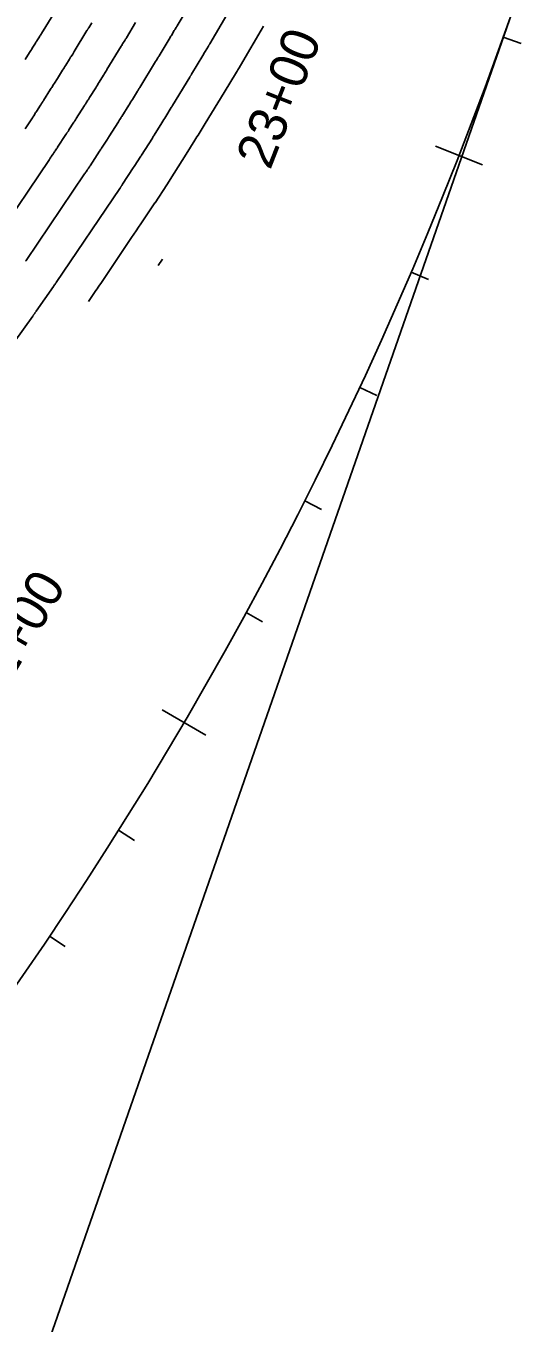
# Model space of a CAD drawing. Extents: x 1710723 to 1713003, y 548603 to 551142.
# Drawn here: x 1712301.3 to 1712379.8, y 549302.6 to 549508.2 of the extents above; entities that cross this region are included whole.
import ezdxf

# ---------------------------------------------------------------- set-up
doc = ezdxf.new("R2010")
doc.units = 0
for name, color, linetype in [('R_Contours', 7, 'Continuous'), ('R_Horz Alg', 7, 'Continuous'), ('R_Horz Alg Annot', 7, 'Continuous')]:
    doc.layers.add(name, color=color, linetype=linetype)

msp = doc.modelspace()

# ---------------------------------------------------------------- linework, layer by layer
at = {"layer": 'R_Contours'}
for points in [[(1712301.23, 549470.93), (1712301.28, 549471), (1712301.32, 549471.06), (1712310.57, 549484.76), (1712310.59, 549484.79), (1712310.61, 549484.82), (1712310.63, 549484.85), (1712310.65, 549484.88), (1712310.73, 549485), (1712310.75, 549485.03), (1712310.77, 549485.06), (1712310.79, 549485.08), (1712310.81, 549485.11), (1712310.97, 549485.35), (1712311.01, 549485.4), (1712311.05, 549485.45), (1712311.12, 549485.56), (1712311.14, 549485.59), (1712311.16, 549485.61), (1712311.18, 549485.64), (1712311.19, 549485.67), (1712311.33, 549485.88), (1712311.36, 549485.92), (1712311.39, 549485.97), (1712311.42, 549486.01), (1712311.45, 549486.06), (1712312.95, 549488.36), (1712313.01, 549488.44), (1712313.06, 549488.52), (1712313.16, 549488.68), (1712313.19, 549488.72), (1712313.22, 549488.76), (1712313.24, 549488.8), (1712313.27, 549488.84), (1712314.19, 549490.26), (1712314.23, 549490.32), (1712314.27, 549490.38), (1712314.35, 549490.51), (1712314.37, 549490.54), (1712314.39, 549490.57), (1712314.41, 549490.6), (1712314.43, 549490.63), (1712315.94, 549493.03), (1712315.98, 549493.1), (1712316.03, 549493.17), (1712316.07, 549493.25), (1712316.12, 549493.32), (1712316.3, 549493.6), (1712316.34, 549493.67), (1712316.39, 549493.74), (1712316.43, 549493.81), (1712316.48, 549493.88), (1712317.58, 549495.65), (1712317.72, 549495.88), (1712317.86, 549496.11), (1712318.01, 549496.34), (1712318.15, 549496.57), (1712318.94, 549497.85), (1712318.97, 549497.9), (1712319, 549497.95), (1712319.03, 549498), (1712319.06, 549498.05), (1712319.19, 549498.26), (1712319.22, 549498.31), (1712319.26, 549498.36), (1712319.29, 549498.41), (1712319.32, 549498.46), (1712321.82, 549502.56), (1712321.83, 549502.58), (1712321.84, 549502.6), (1712321.86, 549502.62), (1712321.87, 549502.64), (1712321.92, 549502.72), (1712321.94, 549502.76), (1712321.96, 549502.79), (1712322.2, 549503.17), (1712322.24, 549503.24), (1712322.29, 549503.31), (1712322.33, 549503.38), (1712322.37, 549503.45), (1712323.98, 549506.13), (1712324.07, 549506.27), (1712324.15, 549506.42), (1712324.24, 549506.57), (1712324.33, 549506.71), (1712324.78, 549507.47), (1712324.81, 549507.53), (1712324.85, 549507.59), (1712324.89, 549507.65), (1712324.93, 549507.71), (1712325.08, 549507.96), (1712325.12, 549508.02), (1712325.15, 549508.09), (1712325.19, 549508.15), (1712325.23, 549508.21), (1712327.68, 549512.37)], [(1712296.57, 549474.59), (1712304.99, 549487.06), (1712305.02, 549487.11), (1712305.05, 549487.15), (1712305.08, 549487.19), (1712305.11, 549487.24), (1712305.23, 549487.41), (1712305.26, 549487.46), (1712305.29, 549487.5), (1712305.32, 549487.54), (1712305.35, 549487.59), (1712305.59, 549487.93), (1712305.62, 549487.97), (1712305.65, 549488.01), (1712305.67, 549488.05), (1712305.7, 549488.09), (1712305.81, 549488.25), (1712305.84, 549488.29), (1712305.87, 549488.33), (1712305.89, 549488.37), (1712305.92, 549488.41), (1712306.13, 549488.73), (1712306.17, 549488.8), (1712306.22, 549488.86), (1712306.26, 549488.93), (1712306.3, 549488.99), (1712307.62, 549491.02), (1712307.66, 549491.08), (1712307.7, 549491.14), (1712307.74, 549491.2), (1712307.78, 549491.26), (1712307.94, 549491.49), (1712307.98, 549491.55), (1712308.01, 549491.61), (1712308.05, 549491.67), (1712308.09, 549491.73), (1712308.89, 549492.96), (1712308.92, 549493.01), (1712308.95, 549493.06), (1712308.98, 549493.1), (1712309.01, 549493.15), (1712309.13, 549493.33), (1712309.16, 549493.38), (1712309.19, 549493.42), (1712309.22, 549493.47), (1712309.25, 549493.52), (1712310.56, 549495.61), (1712310.63, 549495.72), (1712310.7, 549495.82), (1712310.76, 549495.93), (1712310.83, 549496.03), (1712311.1, 549496.45), (1712311.17, 549496.56), (1712311.24, 549496.66), (1712311.3, 549496.77), (1712311.37, 549496.87), (1712312.33, 549498.43), (1712312.47, 549498.64), (1712312.6, 549498.85), (1712312.73, 549499.07), (1712312.86, 549499.28), (1712313.55, 549500.4), (1712313.6, 549500.47), (1712313.65, 549500.55), (1712313.69, 549500.63), (1712313.74, 549500.7), (1712313.93, 549501.01), (1712313.98, 549501.08), (1712314.03, 549501.16), (1712314.08, 549501.24), (1712314.12, 549501.31), (1712316.38, 549505.02), (1712316.4, 549505.05), (1712316.42, 549505.08), (1712316.44, 549505.11), (1712316.45, 549505.13), (1712316.53, 549505.25), (1712316.54, 549505.28), (1712316.56, 549505.31), (1712316.58, 549505.34), (1712316.6, 549505.36), (1712316.95, 549505.93), (1712317.02, 549506.03), (1712317.08, 549506.14), (1712317.14, 549506.24), (1712317.21, 549506.35), (1712318.64, 549508.74)], [(1712299.4, 549458.07), (1712302.36, 549462.24), (1712302.39, 549462.28), (1712302.42, 549462.33), (1712302.45, 549462.37), (1712302.48, 549462.41), (1712302.61, 549462.6), (1712302.63, 549462.63), (1712302.66, 549462.66), (1712302.68, 549462.69), (1712302.7, 549462.73), (1712302.8, 549462.86), (1712302.82, 549462.89), (1712302.85, 549462.92), (1712302.87, 549462.96), (1712302.89, 549462.99), (1712305.65, 549466.93), (1712305.66, 549466.95), (1712305.7, 549467.01), (1712305.71, 549467.02), (1712305.81, 549467.16), (1712305.83, 549467.18), (1712305.85, 549467.21), (1712305.86, 549467.23), (1712305.88, 549467.26), (1712305.98, 549467.4), (1712306.01, 549467.44), (1712306.03, 549467.47), (1712306.05, 549467.5), (1712306.07, 549467.54), (1712316.15, 549482.46), (1712316.16, 549482.48), (1712316.17, 549482.49), (1712316.18, 549482.51), (1712316.19, 549482.52), (1712316.24, 549482.6), (1712316.27, 549482.64), (1712316.36, 549482.77), (1712316.39, 549482.81), (1712316.43, 549482.87), (1712316.44, 549482.88), (1712316.45, 549482.89), (1712316.46, 549482.91), (1712316.47, 549482.92), (1712316.54, 549483.03), (1712316.57, 549483.07), (1712316.6, 549483.12), (1712318.28, 549485.7), (1712318.32, 549485.76), (1712318.39, 549485.86), (1712318.42, 549485.9), (1712318.44, 549485.94), (1712319.49, 549487.56), (1712319.53, 549487.62), (1712319.57, 549487.68), (1712319.58, 549487.7), (1712319.59, 549487.71), (1712319.6, 549487.73), (1712319.61, 549487.75), (1712321.31, 549490.45), (1712321.33, 549490.49), (1712321.36, 549490.53), (1712321.38, 549490.56), (1712321.4, 549490.6), (1712321.49, 549490.74), (1712321.52, 549490.77), (1712321.54, 549490.81), (1712321.56, 549490.85), (1712321.58, 549490.88), (1712322.82, 549492.87), (1712322.98, 549493.12), (1712323.13, 549493.37), (1712323.28, 549493.62), (1712323.44, 549493.86), (1712324.32, 549495.3), (1712324.34, 549495.32), (1712324.35, 549495.35), (1712324.37, 549495.38), (1712324.38, 549495.4), (1712324.45, 549495.5), (1712324.47, 549495.53), (1712324.48, 549495.56), (1712324.5, 549495.58), (1712324.51, 549495.61), (1712327.26, 549500.11), (1712327.27, 549500.13), (1712327.28, 549500.15), (1712327.31, 549500.2), (1712327.33, 549500.23), (1712327.45, 549500.42), (1712327.47, 549500.45), (1712327.49, 549500.49), (1712327.52, 549500.52), (1712327.54, 549500.56), (1712329.31, 549503.52), (1712329.41, 549503.67), (1712329.5, 549503.83), (1712329.59, 549503.99), (1712329.69, 549504.14), (1712330.21, 549505.03), (1712330.23, 549505.06), (1712330.25, 549505.09), (1712330.27, 549505.12), (1712330.29, 549505.15), (1712330.37, 549505.28), (1712330.39, 549505.31), (1712330.41, 549505.34), (1712330.42, 549505.37), (1712330.44, 549505.4), (1712333.13, 549509.96)], [(1712301.15, 549502.87), (1712301.85, 549503.99), (1712301.96, 549504.16), (1712302.07, 549504.34), (1712302.18, 549504.52), (1712302.28, 549504.69), (1712302.78, 549505.5), (1712302.86, 549505.62), (1712302.94, 549505.75), (1712303.02, 549505.88), (1712303.1, 549506), (1712303.42, 549506.51), (1712303.5, 549506.63), (1712303.58, 549506.76), (1712303.66, 549506.89), (1712303.73, 549507.02), (1712305.51, 549509.93)], [(1712311.7, 549508.69), (1712311.23, 549507.93), (1712311.21, 549507.9), (1712311.19, 549507.86), (1712311.16, 549507.82), (1712311.14, 549507.78), (1712311.04, 549507.63), (1712311.02, 549507.59), (1712310.99, 549507.55), (1712310.97, 549507.51), (1712310.95, 549507.47), (1712308.93, 549504.16), (1712308.87, 549504.06), (1712308.8, 549503.96), (1712308.74, 549503.86), (1712308.68, 549503.76), (1712308.42, 549503.35), (1712308.36, 549503.25), (1712308.29, 549503.15), (1712308.23, 549503.05), (1712308.17, 549502.95), (1712307.57, 549501.98), (1712307.45, 549501.79), (1712307.33, 549501.6), (1712307.21, 549501.4), (1712307.09, 549501.21), (1712306.26, 549499.87), (1712306.17, 549499.73), (1712306.08, 549499.59), (1712305.99, 549499.45), (1712305.91, 549499.31), (1712305.55, 549498.75), (1712305.46, 549498.61), (1712305.37, 549498.47), (1712305.28, 549498.33), (1712305.19, 549498.19), (1712304.06, 549496.4), (1712304.03, 549496.34), (1712303.99, 549496.28), (1712303.95, 549496.22), (1712303.91, 549496.15), (1712303.75, 549495.91), (1712303.71, 549495.85), (1712303.67, 549495.79), (1712303.63, 549495.73), (1712303.59, 549495.67), (1712302.92, 549494.63), (1712302.87, 549494.55), (1712302.81, 549494.47), (1712302.76, 549494.39), (1712302.71, 549494.31), (1712302.5, 549493.99), (1712302.45, 549493.91), (1712302.4, 549493.83), (1712302.35, 549493.75), (1712302.29, 549493.67), (1712301.16, 549491.93)], [(1712338.94, 549508.19), (1712338.57, 549507.55), (1712335.66, 549502.6), (1712335.65, 549502.59), (1712335.05, 549501.58), (1712334.95, 549501.41), (1712334.85, 549501.24), (1712334.75, 549501.07), (1712334.65, 549500.9), (1712332.7, 549497.67), (1712332.69, 549497.65), (1712329.71, 549492.76), (1712329.71, 549492.75), (1712328.72, 549491.16), (1712328.56, 549490.89), (1712328.39, 549490.63), (1712328.23, 549490.36), (1712328.07, 549490.1), (1712326.69, 549487.88), (1712326.68, 549487.87), (1712324.79, 549484.86), (1712324.79, 549484.86), (1712323.62, 549483.05), (1712323.61, 549483.04), (1712321.74, 549480.18), (1712321.73, 549480.16), (1712319.5, 549476.86), (1712319.13, 549476.31), (1712318.76, 549475.76), (1712318.39, 549475.21), (1712318.01, 549474.66), (1712313.12, 549467.4), (1712312.93, 549467.12), (1712312.74, 549466.83), (1712312.54, 549466.54), (1712312.35, 549466.26), (1712311.19, 549464.53)], [(1712322.94, 549471.27), (1712322.24, 549470.23)]]:
    msp.add_lwpolyline(points, dxfattribs=at)
at = {"layer": 'R_Horz Alg'}
msp.add_arc((1711777.17, 549719.88), 636.62, 271.07865, 340.7734, dxfattribs=at)
at = {"layer": 'R_Horz Alg Annot'}
msp.add_line((1712232.32, 549091.72), (1712378.29, 549510.24), dxfattribs=at)
for points in [[(1712379.77, 549505.41), (1712376.94, 549506.42)], [(1712366.21, 549489.14), (1712373.66, 549486.22)], [(1712365.11, 549468), (1712362.35, 549469.18)], [(1712356.91, 549449.65), (1712354.19, 549450.92)], [(1712348.13, 549431.58), (1712345.46, 549432.93)], [(1712338.8, 549413.79), (1712336.16, 549415.22)], [(1712322.87, 549399.84), (1712329.77, 549395.79)], [(1712318.47, 549379.12), (1712315.93, 549380.72)], [(1712307.5, 549362.29), (1712305.01, 549363.97)]]:
    msp.add_lwpolyline(points, dxfattribs=at)

# ---------------------------------------------------------------- texts
for s, rotation, p in [('23+00', 68.6088, (1712339.98, 549485.24)), ('22+00', 59.6088, (1712296.35, 549400.08))]:
    msp.add_text(s, height=6, rotation=rotation, dxfattribs=at).set_placement(p)

doc.saveas('drawing.dxf')
